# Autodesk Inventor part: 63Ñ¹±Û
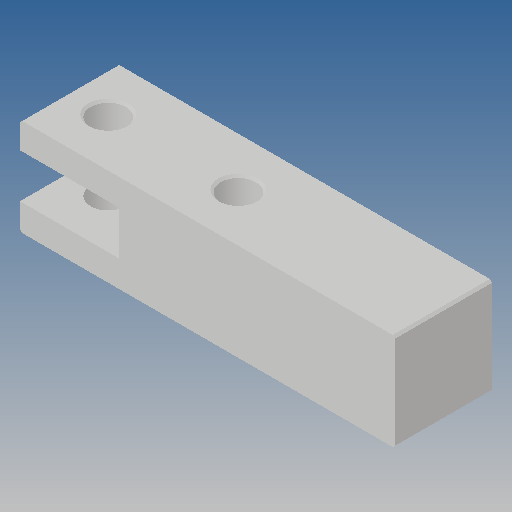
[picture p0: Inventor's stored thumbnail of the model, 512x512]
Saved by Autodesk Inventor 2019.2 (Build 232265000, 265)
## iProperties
Created: 2013-07
Part Number: 63Ñ¹±Û
Material: Ogólny
Document SubType Name: Modeling
Designer: CADENGINEERING4
Density: 1 g/cm^3
Appearance: Domyślna
Author: CADENGINEERING4
Revision Number: ÈÎºÎ
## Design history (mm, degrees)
feature "µ¹½Ç1"
node "Bryła1"
